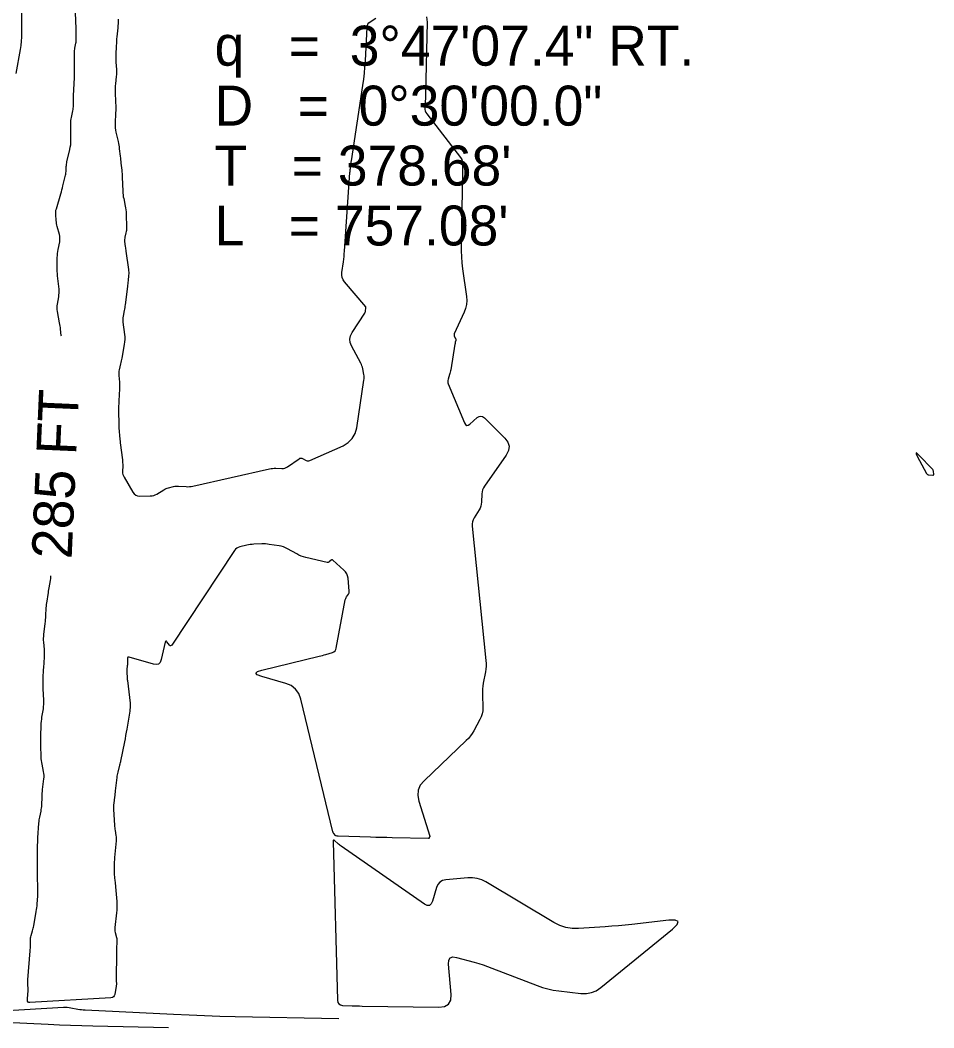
# Model space of a CAD drawing. Extents: x 1768942 to 1774819, y 723037 to 732099.
# Drawn here: x 1770557.3 to 1770694.5, y 730069.8 to 730221.1 of the extents above; entities that cross this region are included whole.
import ezdxf

# ---------------------------------------------------------------- set-up
doc = ezdxf.new("R2010")
doc.units = 0
for name, color, linetype in [('R_Contour Annot', 7, 'Continuous'), ('R_Contours', 7, 'Continuous'), ('R_Horz Alg Annot', 7, 'Continuous')]:
    doc.layers.add(name, color=color, linetype=linetype)

msp = doc.modelspace()

# ---------------------------------------------------------------- linework, layer by layer
at = {"layer": 'R_Contours'}
for points in [[(1770557.5, 730222.68), (1770557.51, 730219.14), (1770557.5, 730218.53), (1770557.46, 730217.92), (1770557.39, 730217.31), (1770557.29, 730216.71), (1770556.62, 730213.09)], [(1770563.47, 730173.64), (1770563.46, 730173.75), (1770563.35, 730174.69), (1770563.32, 730174.93), (1770563.29, 730175.16), (1770563.25, 730175.4), (1770563.21, 730175.63), (1770562.87, 730177.37), (1770562.83, 730177.65), (1770562.82, 730177.92), (1770562.83, 730178.2), (1770562.87, 730178.47), (1770563.07, 730179.57), (1770563.11, 730179.85), (1770563.14, 730180.12), (1770563.14, 730180.4), (1770563.12, 730180.68), (1770562.91, 730182.7), (1770562.88, 730183.04), (1770562.85, 730183.37), (1770562.84, 730183.71), (1770562.84, 730184.04), (1770562.86, 730185.47), (1770562.87, 730185.77), (1770562.89, 730186.06), (1770562.93, 730186.35), (1770562.98, 730186.64), (1770563.22, 730187.81), (1770563.26, 730188.08), (1770563.26, 730188.36), (1770563.24, 730188.64), (1770563.18, 730188.91), (1770562.85, 730190.12), (1770562.8, 730190.33), (1770562.76, 730190.55), (1770562.72, 730190.77), (1770562.7, 730191), (1770562.62, 730191.89), (1770562.62, 730192.11), (1770562.63, 730192.34), (1770562.66, 730192.55), (1770562.72, 730192.77), (1770563.39, 730195.04), (1770563.48, 730195.33), (1770563.56, 730195.62), (1770563.64, 730195.92), (1770563.71, 730196.21), (1770564.06, 730197.62), (1770564.1, 730197.8), (1770564.13, 730197.99), (1770564.16, 730198.17), (1770564.17, 730198.36), (1770564.21, 730199.1), (1770564.22, 730199.28), (1770564.24, 730199.47), (1770564.27, 730199.65), (1770564.31, 730199.83), (1770564.74, 730201.65), (1770564.81, 730202.02), (1770564.87, 730202.39), (1770564.9, 730202.76), (1770564.9, 730203.13), (1770564.88, 730205.59), (1770564.89, 730205.82), (1770564.9, 730206.05), (1770564.93, 730206.28), (1770564.98, 730206.5), (1770565.19, 730207.49), (1770565.23, 730207.68), (1770565.25, 730207.87), (1770565.27, 730208.06), (1770565.28, 730208.25), (1770565.29, 730209.02), (1770565.29, 730209.22), (1770565.29, 730209.41), (1770565.3, 730209.6), (1770565.31, 730209.8), (1770565.42, 730212.42), (1770565.43, 730212.83), (1770565.44, 730213.24), (1770565.45, 730213.66), (1770565.45, 730214.07), (1770565.44, 730216.18), (1770565.44, 730216.36), (1770565.46, 730216.55), (1770565.48, 730216.73), (1770565.51, 730216.91), (1770565.64, 730217.63), (1770565.67, 730217.81), (1770565.69, 730217.98), (1770565.7, 730218.16), (1770565.7, 730218.35), (1770565.7, 730219.07), (1770565.7, 730219.25), (1770565.7, 730219.43), (1770565.69, 730219.61), (1770565.69, 730219.79), (1770565.58, 730222.23)], [(1770618.3, 730221.6), (1770618.4, 730220.8), (1770618.16, 730209.98), (1770618.16, 730209.73), (1770618.15, 730209.47), (1770618.14, 730209.22), (1770618.12, 730208.96), (1770618.06, 730207.94), (1770618.07, 730207.69), (1770618.12, 730207.46), (1770618.21, 730207.24), (1770618.35, 730207.03), (1770623.4, 730200.49), (1770623.52, 730200.33), (1770623.6, 730200.15), (1770623.65, 730199.96), (1770623.67, 730199.76), (1770623.7, 730198.94), (1770623.71, 730198.74), (1770623.71, 730198.53), (1770623.71, 730198.33), (1770623.71, 730198.13), (1770623.52, 730187.38), (1770623.52, 730186.48), (1770623.56, 730185.57), (1770623.63, 730184.67), (1770623.73, 730183.77), (1770624.3, 730179.61), (1770624.34, 730178.99), (1770624.29, 730178.4), (1770624.16, 730177.81), (1770623.95, 730177.23), (1770622.47, 730174), (1770622.44, 730173.91), (1770622.44, 730173.83), (1770622.45, 730173.75), (1770622.48, 730173.66), (1770622.66, 730173.3), (1770622.69, 730173.23), (1770622.7, 730173.16), (1770622.71, 730173.09), (1770622.7, 730173.01), (1770622.63, 730172.72), (1770622.62, 730172.64), (1770622.6, 730172.57), (1770622.59, 730172.49), (1770622.58, 730172.42), (1770621.93, 730168.6), (1770621.9, 730168.42), (1770621.86, 730168.24), (1770621.81, 730168.06), (1770621.76, 730167.89), (1770621.54, 730167.18), (1770621.5, 730167.01), (1770621.49, 730166.83), (1770621.52, 730166.66), (1770621.57, 730166.49), (1770623.99, 730160.63), (1770624.15, 730160.36), (1770624.34, 730160.24), (1770624.56, 730160.26), (1770624.82, 730160.43), (1770625.92, 730161.41), (1770626.2, 730161.6), (1770626.47, 730161.65), (1770626.73, 730161.58), (1770627, 730161.38), (1770630.04, 730158.35), (1770630.5, 730157.74), (1770630.7, 730157.11), (1770630.62, 730156.46), (1770630.27, 730155.78), (1770627.01, 730151.11), (1770626.85, 730150.85), (1770626.73, 730150.57), (1770626.65, 730150.28), (1770626.62, 730149.97), (1770626.56, 730148.72), (1770626.53, 730148.42), (1770626.46, 730148.12), (1770626.35, 730147.84), (1770626.2, 730147.56), (1770625.46, 730146.37), (1770625.31, 730146.08), (1770625.21, 730145.77), (1770625.17, 730145.45), (1770625.18, 730145.12), (1770627.23, 730124.93), (1770627.26, 730124.5), (1770627.25, 730124.07), (1770627.22, 730123.65), (1770627.15, 730123.23), (1770626.83, 730121.54), (1770626.76, 730121.11), (1770626.71, 730120.69), (1770626.69, 730120.26), (1770626.69, 730119.83), (1770626.75, 730117.85), (1770626.74, 730117.39), (1770626.66, 730116.94), (1770626.52, 730116.5), (1770626.33, 730116.08), (1770625.41, 730114.4), (1770625.16, 730113.99), (1770624.89, 730113.61), (1770624.59, 730113.25), (1770624.26, 730112.91), (1770617.93, 730106.89), (1770617.37, 730106.22), (1770617.06, 730105.49), (1770616.98, 730104.69), (1770617.14, 730103.84), (1770618.78, 730098.59), (1770618.78, 730098.56), (1770618.79, 730098.52), (1770618.78, 730098.48), (1770618.77, 730098.45), (1770618.72, 730098.3), (1770618.7, 730098.27), (1770618.68, 730098.25), (1770618.65, 730098.24), (1770618.61, 730098.23), (1770613.17, 730098.33), (1770612.35, 730098.35), (1770611.53, 730098.37), (1770610.71, 730098.39), (1770609.89, 730098.42), (1770605.06, 730098.57), (1770605.02, 730098.57), (1770604.98, 730098.57), (1770604.95, 730098.58), (1770604.91, 730098.58), (1770604.76, 730098.61), (1770604.72, 730098.62), (1770604.69, 730098.63), (1770604.66, 730098.65), (1770604.63, 730098.68), (1770604.38, 730098.96), (1770604.34, 730099.02), (1770604.3, 730099.09), (1770604.27, 730099.15), (1770604.25, 730099.23), (1770599.42, 730119.16), (1770599.11, 730119.99), (1770598.64, 730120.66), (1770597.99, 730121.17), (1770597.17, 730121.51), (1770593.56, 730122.54), (1770592.89, 730122.8), (1770592.67, 730123.04), (1770592.9, 730123.28), (1770593.59, 730123.5), (1770602.19, 730125.57), (1770602.44, 730125.64), (1770602.69, 730125.7), (1770602.94, 730125.77), (1770603.19, 730125.85), (1770604.18, 730126.16), (1770604.4, 730126.25), (1770604.57, 730126.4), (1770604.69, 730126.59), (1770604.76, 730126.82), (1770606.1, 730134.03), (1770606.12, 730134.15), (1770606.17, 730134.27), (1770606.22, 730134.38), (1770606.29, 730134.49), (1770606.59, 730134.9), (1770606.65, 730135.01), (1770606.69, 730135.12), (1770606.71, 730135.24), (1770606.71, 730135.36), (1770606.53, 730137.29), (1770606.46, 730137.64), (1770606.34, 730137.96), (1770606.16, 730138.24), (1770605.91, 730138.5), (1770604.24, 730139.99), (1770604.17, 730140.04), (1770604.1, 730140.05), (1770604.04, 730140.04), (1770603.97, 730139.99), (1770603.7, 730139.75), (1770603.63, 730139.7), (1770603.55, 730139.67), (1770603.47, 730139.66), (1770603.39, 730139.67), (1770600.2, 730140.41), (1770599.84, 730140.51), (1770599.49, 730140.63), (1770599.15, 730140.78), (1770598.81, 730140.95), (1770597.45, 730141.72), (1770597.14, 730141.88), (1770596.83, 730142), (1770596.5, 730142.1), (1770596.17, 730142.16), (1770594.69, 730142.38), (1770594.41, 730142.41), (1770594.12, 730142.44), (1770593.84, 730142.44), (1770593.55, 730142.44), (1770592.37, 730142.39), (1770592.11, 730142.37), (1770591.84, 730142.34), (1770591.58, 730142.3), (1770591.32, 730142.24), (1770590.28, 730142), (1770590.04, 730141.92), (1770589.82, 730141.8), (1770589.63, 730141.64), (1770589.47, 730141.44), (1770580.05, 730127.27), (1770579.96, 730127.18), (1770579.88, 730127.14), (1770579.79, 730127.17), (1770579.69, 730127.26), (1770579.32, 730127.75), (1770579.24, 730127.84), (1770579.17, 730127.86), (1770579.11, 730127.81), (1770579.07, 730127.7), (1770578.47, 730125.07), (1770578.31, 730124.66), (1770578.07, 730124.41), (1770577.72, 730124.32), (1770577.29, 730124.38), (1770573.66, 730125.44), (1770573.55, 730125.45), (1770573.47, 730125.43), (1770573.42, 730125.36), (1770573.4, 730125.24), (1770573.4, 730124.69), (1770573.4, 730124.55), (1770573.39, 730124.41), (1770573.38, 730124.28), (1770573.37, 730124.14), (1770573.32, 730123.59), (1770573.31, 730123.45), (1770573.3, 730123.31), (1770573.3, 730123.18), (1770573.3, 730123.04), (1770573.33, 730122.48), (1770573.34, 730122.34), (1770573.35, 730122.2), (1770573.36, 730122.07), (1770573.38, 730121.93), (1770573.8, 730118.52), (1770573.81, 730118.42), (1770573.81, 730118.32), (1770573.81, 730118.22), (1770573.81, 730118.12), (1770573.78, 730117.73), (1770573.77, 730117.63), (1770573.76, 730117.53), (1770573.75, 730117.44), (1770573.73, 730117.34), (1770573.29, 730114.64), (1770573.21, 730114.16), (1770573.12, 730113.68), (1770573.03, 730113.2), (1770572.94, 730112.72), (1770572.36, 730109.83), (1770572.35, 730109.77), (1770572.34, 730109.72), (1770572.33, 730109.67), (1770572.31, 730109.62), (1770572.26, 730109.42), (1770572.25, 730109.37), (1770572.23, 730109.31), (1770572.22, 730109.26), (1770572.21, 730109.21), (1770571.94, 730108.17), (1770571.89, 730107.98), (1770571.86, 730107.79), (1770571.82, 730107.59), (1770571.8, 730107.4), (1770571.56, 730105.38), (1770571.54, 730105.15), (1770571.51, 730104.91), (1770571.48, 730104.67), (1770571.45, 730104.44), (1770571.33, 730103.5), (1770571.31, 730103.26), (1770571.3, 730103.02), (1770571.3, 730102.79), (1770571.31, 730102.55), (1770571.46, 730100.2), (1770571.47, 730100.01), (1770571.49, 730099.81), (1770571.52, 730099.62), (1770571.55, 730099.42), (1770571.67, 730098.65), (1770571.7, 730098.45), (1770571.71, 730098.26), (1770571.71, 730098.06), (1770571.7, 730097.87), (1770571.46, 730095.37), (1770571.45, 730095.16), (1770571.43, 730094.95), (1770571.42, 730094.74), (1770571.41, 730094.54), (1770571.39, 730093.7), (1770571.39, 730093.49), (1770571.39, 730093.29), (1770571.4, 730093.08), (1770571.42, 730092.87), (1770571.52, 730091.88), (1770571.55, 730091.64), (1770571.57, 730091.41), (1770571.59, 730091.17), (1770571.61, 730090.94), (1770571.78, 730088.74), (1770571.8, 730088.32), (1770571.8, 730087.89), (1770571.79, 730087.46), (1770571.75, 730087.04), (1770571.51, 730084.87), (1770571.5, 730084.68), (1770571.5, 730084.49), (1770571.52, 730084.3), (1770571.56, 730084.11), (1770571.75, 730083.37), (1770571.79, 730083.19), (1770571.81, 730083), (1770571.82, 730082.81), (1770571.82, 730082.62), (1770571.76, 730081.81), (1770571.75, 730081.61), (1770571.74, 730081.41), (1770571.73, 730081.21), (1770571.73, 730081.01), (1770571.71, 730077.16), (1770571.71, 730077.07), (1770571.71, 730076.97), (1770571.71, 730076.88), (1770571.72, 730076.79), (1770571.73, 730076.42), (1770571.74, 730076.32), (1770571.73, 730076.23), (1770571.72, 730076.14), (1770571.71, 730076.05), (1770571.48, 730074.8), (1770571.41, 730074.59), (1770571.29, 730074.43), (1770571.13, 730074.33), (1770570.91, 730074.29), (1770558.76, 730073.58), (1770558.59, 730073.59), (1770558.47, 730073.66), (1770558.4, 730073.78), (1770558.39, 730073.95), (1770558.46, 730074.97), (1770558.46, 730075.05), (1770558.47, 730075.14), (1770558.47, 730075.22), (1770558.47, 730075.31), (1770558.47, 730075.64), (1770558.47, 730075.73), (1770558.47, 730075.81), (1770558.47, 730075.89), (1770558.46, 730075.98), (1770558.42, 730076.52), (1770558.42, 730076.63), (1770558.42, 730076.75), (1770558.42, 730076.87), (1770558.43, 730076.99), (1770558.8, 730081.35), (1770558.81, 730081.54), (1770558.82, 730081.74), (1770558.83, 730081.93), (1770558.83, 730082.13), (1770558.83, 730082.92), (1770558.84, 730083.11), (1770558.86, 730083.29), (1770558.89, 730083.47), (1770558.94, 730083.65), (1770559.16, 730084.37), (1770559.21, 730084.55), (1770559.26, 730084.73), (1770559.3, 730084.91), (1770559.33, 730085.1), (1770559.71, 730087.26), (1770559.76, 730087.54), (1770559.79, 730087.83), (1770559.82, 730088.11), (1770559.85, 730088.4), (1770559.93, 730089.55), (1770559.94, 730089.84), (1770559.95, 730090.13), (1770559.96, 730090.42), (1770559.95, 730090.7), (1770559.9, 730092.61), (1770559.89, 730092.93), (1770559.88, 730093.26), (1770559.88, 730093.58), (1770559.89, 730093.91), (1770559.91, 730095.37), (1770559.91, 730095.62), (1770559.91, 730095.86), (1770559.91, 730096.11), (1770559.91, 730096.36), (1770559.91, 730097.34), (1770559.92, 730097.59), (1770559.92, 730097.84), (1770559.93, 730098.08), (1770559.95, 730098.33), (1770560.1, 730100.54), (1770560.12, 730100.77), (1770560.15, 730101), (1770560.18, 730101.22), (1770560.23, 730101.44), (1770560.42, 730102.33), (1770560.46, 730102.56), (1770560.49, 730102.78), (1770560.52, 730103), (1770560.53, 730103.23), (1770560.57, 730104.45), (1770560.58, 730104.73), (1770560.6, 730105.01), (1770560.62, 730105.28), (1770560.65, 730105.56), (1770560.86, 730107.17), (1770560.88, 730107.45), (1770560.88, 730107.72), (1770560.86, 730108), (1770560.81, 730108.27), (1770560.58, 730109.37), (1770560.53, 730109.64), (1770560.49, 730109.91), (1770560.46, 730110.19), (1770560.45, 730110.47), (1770560.4, 730112.18), (1770560.4, 730112.55), (1770560.39, 730112.91), (1770560.4, 730113.27), (1770560.4, 730113.63), (1770560.44, 730115.17), (1770560.46, 730115.49), (1770560.48, 730115.81), (1770560.52, 730116.13), (1770560.56, 730116.44), (1770560.77, 730117.71), (1770560.81, 730118.02), (1770560.84, 730118.34), (1770560.85, 730118.66), (1770560.84, 730118.98), (1770560.74, 730120.7), (1770560.73, 730120.96), (1770560.72, 730121.22), (1770560.72, 730121.49), (1770560.73, 730121.75), (1770560.76, 730122.81), (1770560.77, 730123.07), (1770560.79, 730123.33), (1770560.8, 730123.6), (1770560.82, 730123.86), (1770560.94, 730125.44), (1770560.96, 730125.73), (1770560.96, 730126.01), (1770560.95, 730126.3), (1770560.93, 730126.58), (1770560.83, 730127.72), (1770560.81, 730128.01), (1770560.81, 730128.29), (1770560.82, 730128.57), (1770560.85, 730128.86), (1770561.04, 730130.52), (1770561.08, 730130.8), (1770561.1, 730131.09), (1770561.13, 730131.37), (1770561.14, 730131.66), (1770561.21, 730132.87), (1770561.22, 730133.12), (1770561.25, 730133.37), (1770561.28, 730133.62), (1770561.32, 730133.87), (1770561.48, 730134.87), (1770561.52, 730135.12), (1770561.56, 730135.36), (1770561.6, 730135.61), (1770561.64, 730135.86), (1770561.84, 730136.98), (1770561.87, 730137.26), (1770561.9, 730137.53), (1770561.9, 730137.67)], [(1770571.99, 730221.26), (1770572, 730220.93), (1770571.99, 730220.59), (1770571.97, 730220.26), (1770571.94, 730219.93), (1770571.8, 730218.59), (1770571.77, 730218.27), (1770571.75, 730217.94), (1770571.73, 730217.61), (1770571.71, 730217.29), (1770571.65, 730215.86), (1770571.64, 730215.59), (1770571.64, 730215.32), (1770571.65, 730215.05), (1770571.66, 730214.79), (1770571.73, 730213.71), (1770571.74, 730213.45), (1770571.74, 730213.18), (1770571.73, 730212.91), (1770571.71, 730212.64), (1770571.59, 730211.51), (1770571.57, 730211.24), (1770571.55, 730210.96), (1770571.55, 730210.68), (1770571.56, 730210.4), (1770571.62, 730208.67), (1770571.63, 730208.3), (1770571.64, 730207.92), (1770571.63, 730207.55), (1770571.62, 730207.17), (1770571.55, 730205.6), (1770571.54, 730205.26), (1770571.56, 730204.93), (1770571.6, 730204.6), (1770571.66, 730204.28), (1770571.98, 730202.86), (1770572.04, 730202.59), (1770572.09, 730202.32), (1770572.13, 730202.05), (1770572.16, 730201.77), (1770572.3, 730200.65), (1770572.33, 730200.39), (1770572.36, 730200.13), (1770572.39, 730199.87), (1770572.42, 730199.61), (1770572.54, 730198.56), (1770572.57, 730198.3), (1770572.59, 730198.04), (1770572.61, 730197.78), (1770572.62, 730197.51), (1770572.69, 730195.43), (1770572.7, 730195.14), (1770572.73, 730194.86), (1770572.77, 730194.58), (1770572.83, 730194.3), (1770573.07, 730193.18), (1770573.12, 730192.9), (1770573.16, 730192.62), (1770573.19, 730192.33), (1770573.2, 730192.05), (1770573.24, 730189.85), (1770573.24, 730189.68), (1770573.23, 730189.51), (1770573.21, 730189.34), (1770573.17, 730189.18), (1770573.01, 730188.51), (1770572.98, 730188.35), (1770572.96, 730188.18), (1770572.96, 730188.01), (1770572.97, 730187.85), (1770573.06, 730187.11), (1770573.08, 730186.93), (1770573.1, 730186.75), (1770573.13, 730186.57), (1770573.15, 730186.39), (1770573.55, 730183.66), (1770573.57, 730183.44), (1770573.58, 730183.23), (1770573.58, 730183.02), (1770573.57, 730182.8), (1770573.48, 730181.94), (1770573.45, 730181.73), (1770573.43, 730181.52), (1770573.4, 730181.3), (1770573.38, 730181.09), (1770573.05, 730178.37), (1770573.02, 730178.15), (1770572.99, 730177.93), (1770572.96, 730177.71), (1770572.92, 730177.49), (1770572.75, 730176.63), (1770572.72, 730176.41), (1770572.7, 730176.19), (1770572.7, 730175.98), (1770572.72, 730175.76), (1770572.95, 730173.91), (1770572.99, 730173.53), (1770572.99, 730173.16), (1770572.97, 730172.78), (1770572.91, 730172.4), (1770572.55, 730170.36), (1770572.51, 730170.14), (1770572.46, 730169.92), (1770572.41, 730169.7), (1770572.36, 730169.48), (1770572.15, 730168.61), (1770572.11, 730168.39), (1770572.08, 730168.18), (1770572.08, 730167.96), (1770572.09, 730167.73), (1770572.19, 730166.73), (1770572.2, 730166.48), (1770572.21, 730166.24), (1770572.21, 730166), (1770572.2, 730165.76), (1770572.1, 730163.92), (1770572.08, 730163.54), (1770572.06, 730163.15), (1770572.06, 730162.77), (1770572.06, 730162.38), (1770572.08, 730160.43), (1770572.09, 730160.2), (1770572.1, 730159.97), (1770572.11, 730159.73), (1770572.13, 730159.5), (1770572.21, 730158.57), (1770572.23, 730158.34), (1770572.25, 730158.11), (1770572.28, 730157.88), (1770572.3, 730157.65), (1770572.63, 730155.06), (1770572.66, 730154.84), (1770572.67, 730154.62), (1770572.68, 730154.4), (1770572.68, 730154.18), (1770572.66, 730153.3), (1770572.67, 730153.08), (1770572.71, 730152.87), (1770572.78, 730152.67), (1770572.88, 730152.48), (1770574.19, 730150.24), (1770574.39, 730149.98), (1770574.63, 730149.79), (1770574.92, 730149.68), (1770575.25, 730149.64), (1770576.83, 730149.66), (1770577.09, 730149.68), (1770577.34, 730149.73), (1770577.58, 730149.82), (1770577.82, 730149.94), (1770578.84, 730150.58), (1770579.01, 730150.67), (1770579.19, 730150.76), (1770579.37, 730150.82), (1770579.56, 730150.88), (1770580.32, 730151.07), (1770580.51, 730151.11), (1770580.7, 730151.14), (1770580.89, 730151.14), (1770581.08, 730151.14), (1770582.21, 730151.05), (1770582.46, 730151.04), (1770582.71, 730151.05), (1770582.96, 730151.07), (1770583.21, 730151.12), (1770594.74, 730153.71), (1770594.97, 730153.75), (1770595.2, 730153.78), (1770595.43, 730153.8), (1770595.66, 730153.8), (1770596.59, 730153.77), (1770596.81, 730153.79), (1770597.03, 730153.83), (1770597.24, 730153.91), (1770597.43, 730154.03), (1770599.17, 730155.25), (1770599.3, 730155.32), (1770599.43, 730155.35), (1770599.56, 730155.33), (1770599.69, 730155.28), (1770600.23, 730154.99), (1770600.37, 730154.94), (1770600.51, 730154.92), (1770600.65, 730154.93), (1770600.78, 730154.98), (1770605.78, 730157.2), (1770606.56, 730157.67), (1770607.16, 730158.27), (1770607.58, 730159.01), (1770607.82, 730159.89), (1770608.9, 730167.04), (1770608.93, 730167.26), (1770608.93, 730167.47), (1770608.92, 730167.69), (1770608.88, 730167.9), (1770608.72, 730168.76), (1770608.67, 730168.97), (1770608.61, 730169.18), (1770608.53, 730169.38), (1770608.43, 730169.57), (1770607.05, 730172.21), (1770606.86, 730172.71), (1770606.81, 730173.21), (1770606.91, 730173.69), (1770607.14, 730174.18), (1770609.04, 730177.11), (1770609.08, 730177.18), (1770609.11, 730177.26), (1770609.13, 730177.34), (1770609.14, 730177.42), (1770609.17, 730177.89), (1770609.17, 730177.9), (1770609.18, 730177.92), (1770609.18, 730177.93), (1770609.18, 730177.94), (1770609.19, 730177.98), (1770609.19, 730178), (1770609.19, 730178.01), (1770609.19, 730178.02), (1770609.18, 730178.03), (1770606.01, 730181.79), (1770605.79, 730182.11), (1770605.65, 730182.45), (1770605.59, 730182.82), (1770605.6, 730183.21), (1770605.82, 730184.8), (1770605.87, 730185.2), (1770605.92, 730185.6), (1770605.96, 730186.01), (1770605.99, 730186.41), (1770606.81, 730198.24), (1770606.82, 730198.39), (1770606.84, 730198.54), (1770606.85, 730198.68), (1770606.87, 730198.83), (1770606.95, 730199.41), (1770606.97, 730199.56), (1770606.99, 730199.7), (1770607.01, 730199.85), (1770607.03, 730199.99), (1770608.75, 730211.29), (1770608.87, 730212.21), (1770608.98, 730213.13), (1770609.06, 730214.06), (1770609.12, 730214.98), (1770609.39, 730220.06), (1770609.43, 730220.29), (1770609.51, 730220.5), (1770609.65, 730220.69), (1770609.83, 730220.84), (1770610.68, 730221.4)], [(1770548.69, 730071.98), (1770563.81, 730072.87), (1770564.08, 730072.88), (1770564.35, 730072.87), (1770564.62, 730072.84), (1770564.89, 730072.8), (1770565.96, 730072.6), (1770566.22, 730072.55), (1770566.49, 730072.52), (1770566.76, 730072.49), (1770567.03, 730072.47), (1770580.33, 730071.83), (1770582.64, 730071.72), (1770584.95, 730071.63), (1770587.26, 730071.56), (1770589.57, 730071.5), (1770605.13, 730071.17)], [(1770579.56, 730069.79), (1770568.22, 730070.03), (1770566.54, 730070.07), (1770564.86, 730070.12), (1770563.18, 730070.19), (1770561.5, 730070.27), (1770551.82, 730070.74)]]:
    msp.add_lwpolyline(points, dxfattribs=at)
for points in [[(1770694.4, 730153.46), (1770694.37, 730153.54), (1770694.33, 730153.62), (1770694.27, 730153.69), (1770692.23, 730155.8), (1770691.94, 730156.07), (1770691.81, 730156.13), (1770691.83, 730155.98), (1770692, 730155.63), (1770693.4, 730153), (1770693.46, 730152.92), (1770693.53, 730152.85), (1770693.62, 730152.82), (1770693.72, 730152.8), (1770694.31, 730152.76), (1770694.33, 730152.76), (1770694.35, 730152.77), (1770694.37, 730152.77), (1770694.39, 730152.77), (1770694.45, 730152.8), (1770694.47, 730152.81), (1770694.48, 730152.82), (1770694.48, 730152.83), (1770694.49, 730152.85), (1770694.42, 730153.37)], [(1770640.16, 730084.7), (1770639.21, 730084.85), (1770638.3, 730085.14), (1770637.42, 730085.59), (1770627.23, 730091.69), (1770626.59, 730092.01), (1770625.92, 730092.22), (1770625.22, 730092.32), (1770624.5, 730092.31), (1770621.18, 730092), (1770620.69, 730091.89), (1770620.3, 730091.67), (1770620.01, 730091.32), (1770619.81, 730090.87), (1770619.2, 730088.8), (1770619.01, 730088.39), (1770618.75, 730088.18), (1770618.42, 730088.18), (1770618.01, 730088.38), (1770605.49, 730097.07), (1770605.36, 730097.16), (1770605.23, 730097.26), (1770605.11, 730097.36), (1770604.99, 730097.46), (1770604.53, 730097.89), (1770604.43, 730097.96), (1770604.35, 730097.97), (1770604.31, 730097.91), (1770604.3, 730097.79), (1770604.95, 730073.92), (1770605, 730073.6), (1770605.15, 730073.37), (1770605.38, 730073.22), (1770605.7, 730073.16), (1770607.16, 730073.11), (1770607.52, 730073.09), (1770607.89, 730073.08), (1770608.25, 730073.07), (1770608.62, 730073.06), (1770620.17, 730072.87), (1770621.02, 730072.98), (1770621.61, 730073.34), (1770621.93, 730073.95), (1770621.99, 730074.81), (1770621.62, 730079.36), (1770621.65, 730079.94), (1770621.87, 730080.3), (1770622.26, 730080.44), (1770622.83, 730080.36), (1770625.48, 730079.63), (1770626.14, 730079.43), (1770626.8, 730079.23), (1770627.45, 730079), (1770628.09, 730078.76), (1770634.93, 730076.14), (1770635.72, 730075.86), (1770636.52, 730075.64), (1770637.34, 730075.46), (1770638.17, 730075.34), (1770641.5, 730074.95), (1770642.32, 730074.93), (1770643.08, 730075.07), (1770643.8, 730075.36), (1770644.47, 730075.82), (1770655.23, 730084.61), (1770655.93, 730085.3), (1770656.07, 730085.74), (1770655.65, 730085.96), (1770654.68, 730085.93), (1770649.13, 730085.32), (1770648.13, 730085.21), (1770647.14, 730085.12), (1770646.14, 730085.04), (1770645.14, 730084.96), (1770641.14, 730084.69)]]:
    msp.add_lwpolyline(points, close=True, dxfattribs=at)

# ---------------------------------------------------------------- texts
at = {"layer": 'R_Contour Annot'}
msp.add_text('285 FT', height=6, rotation=87.4944, dxfattribs=at).set_placement((1770565.01, 730140.11))
at = {"layer": 'R_Horz Alg Annot'}
for s, p in [('q   =  3%%d47\'07.4" RT.', (1770586.48, 730214.26)), ('D   =  0%%d30\'00.0"', (1770586.48, 730205.26)), ("T   = 378.68'", (1770586.48, 730196.26)), ("L   = 757.08'", (1770586.48, 730187.26))]:
    msp.add_text(s, height=6, dxfattribs=at).set_placement(p)

doc.saveas('drawing.dxf')
